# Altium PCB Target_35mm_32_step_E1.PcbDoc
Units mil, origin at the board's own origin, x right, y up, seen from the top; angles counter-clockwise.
Board outline 1400 x 1400 mil, 2 copper layers (Top Layer, Bottom Layer), stack 34.8 mil thick; 3 components, 0 nets, 2 pads, 0 vias.
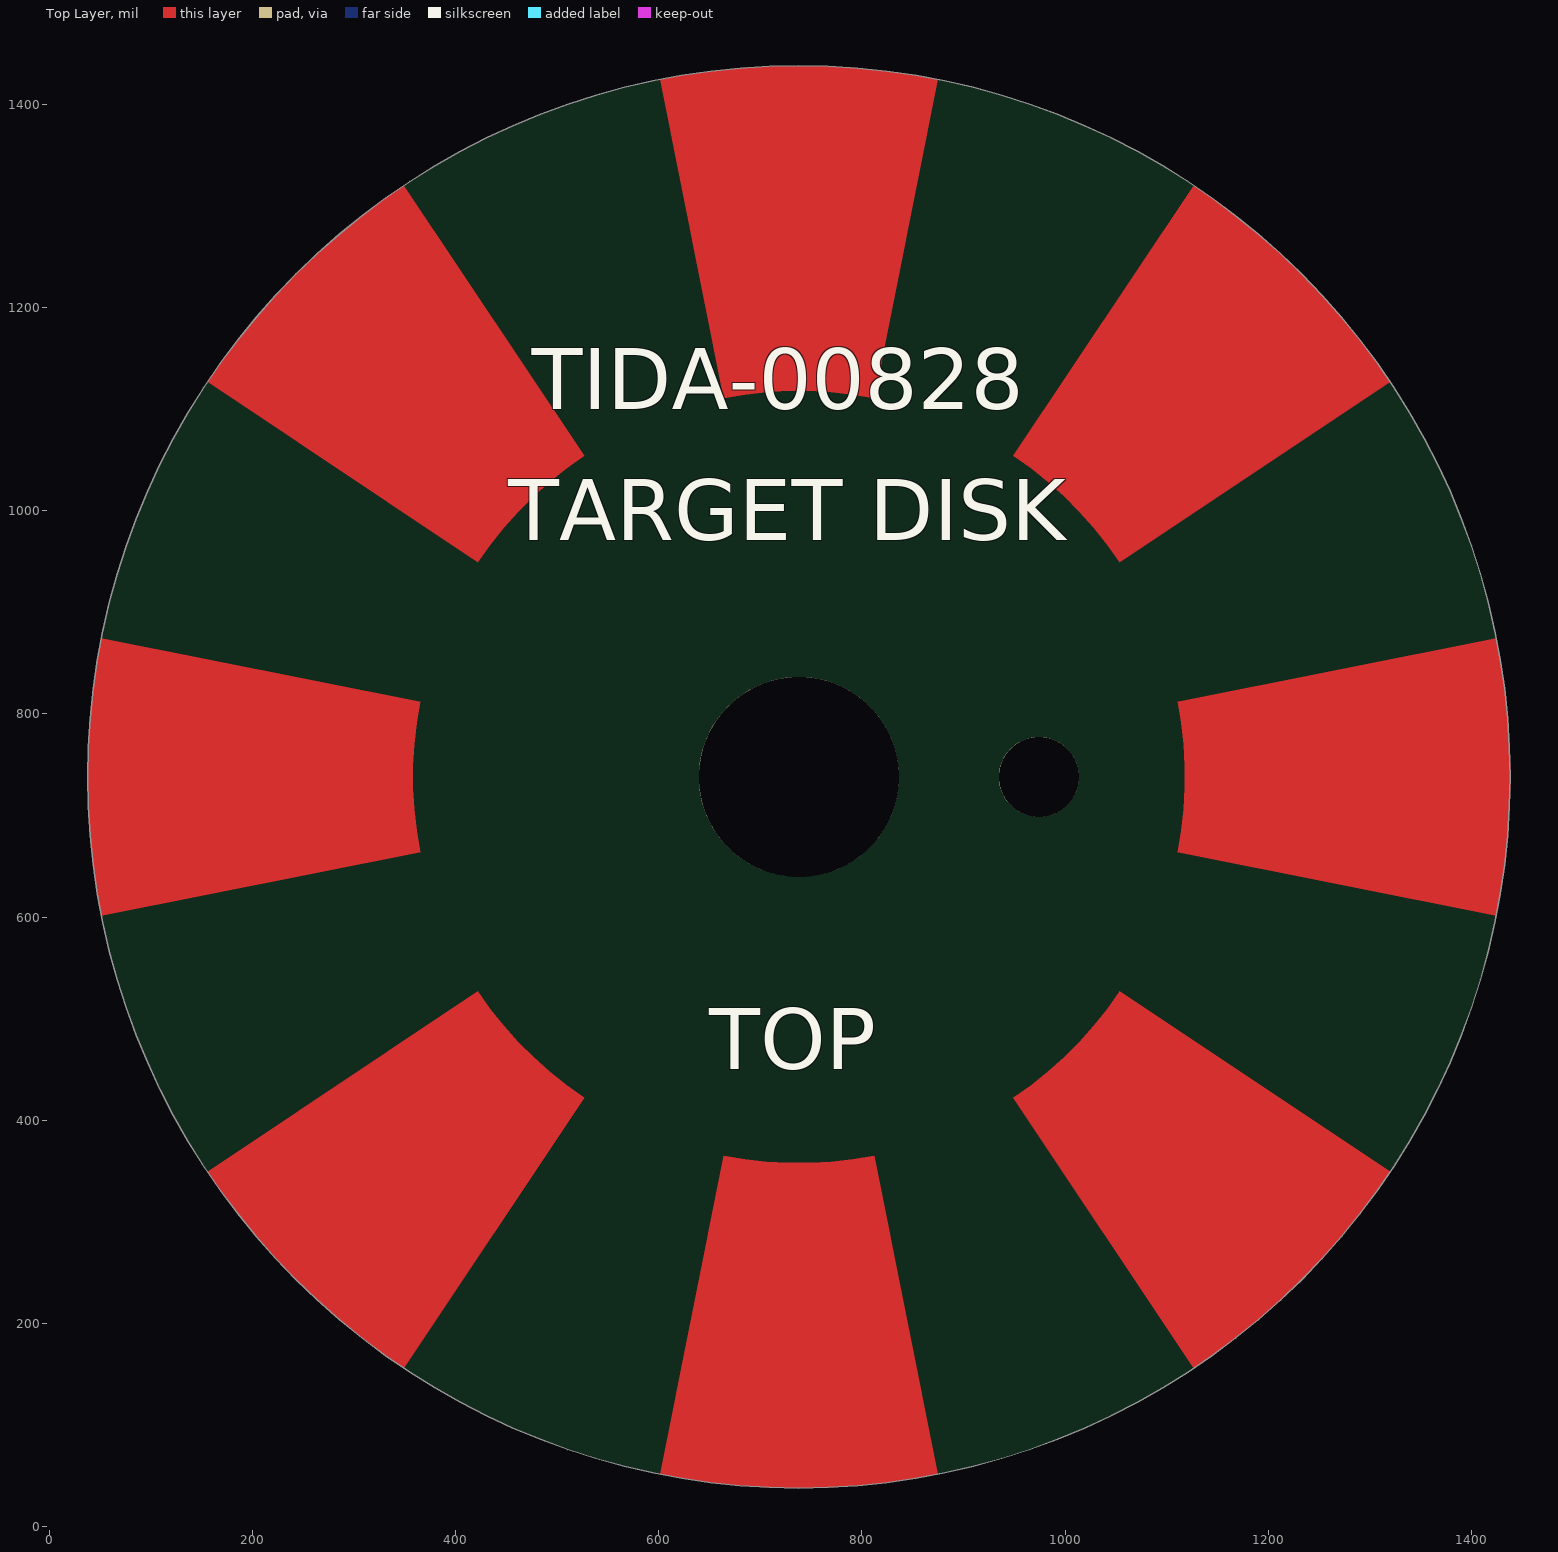
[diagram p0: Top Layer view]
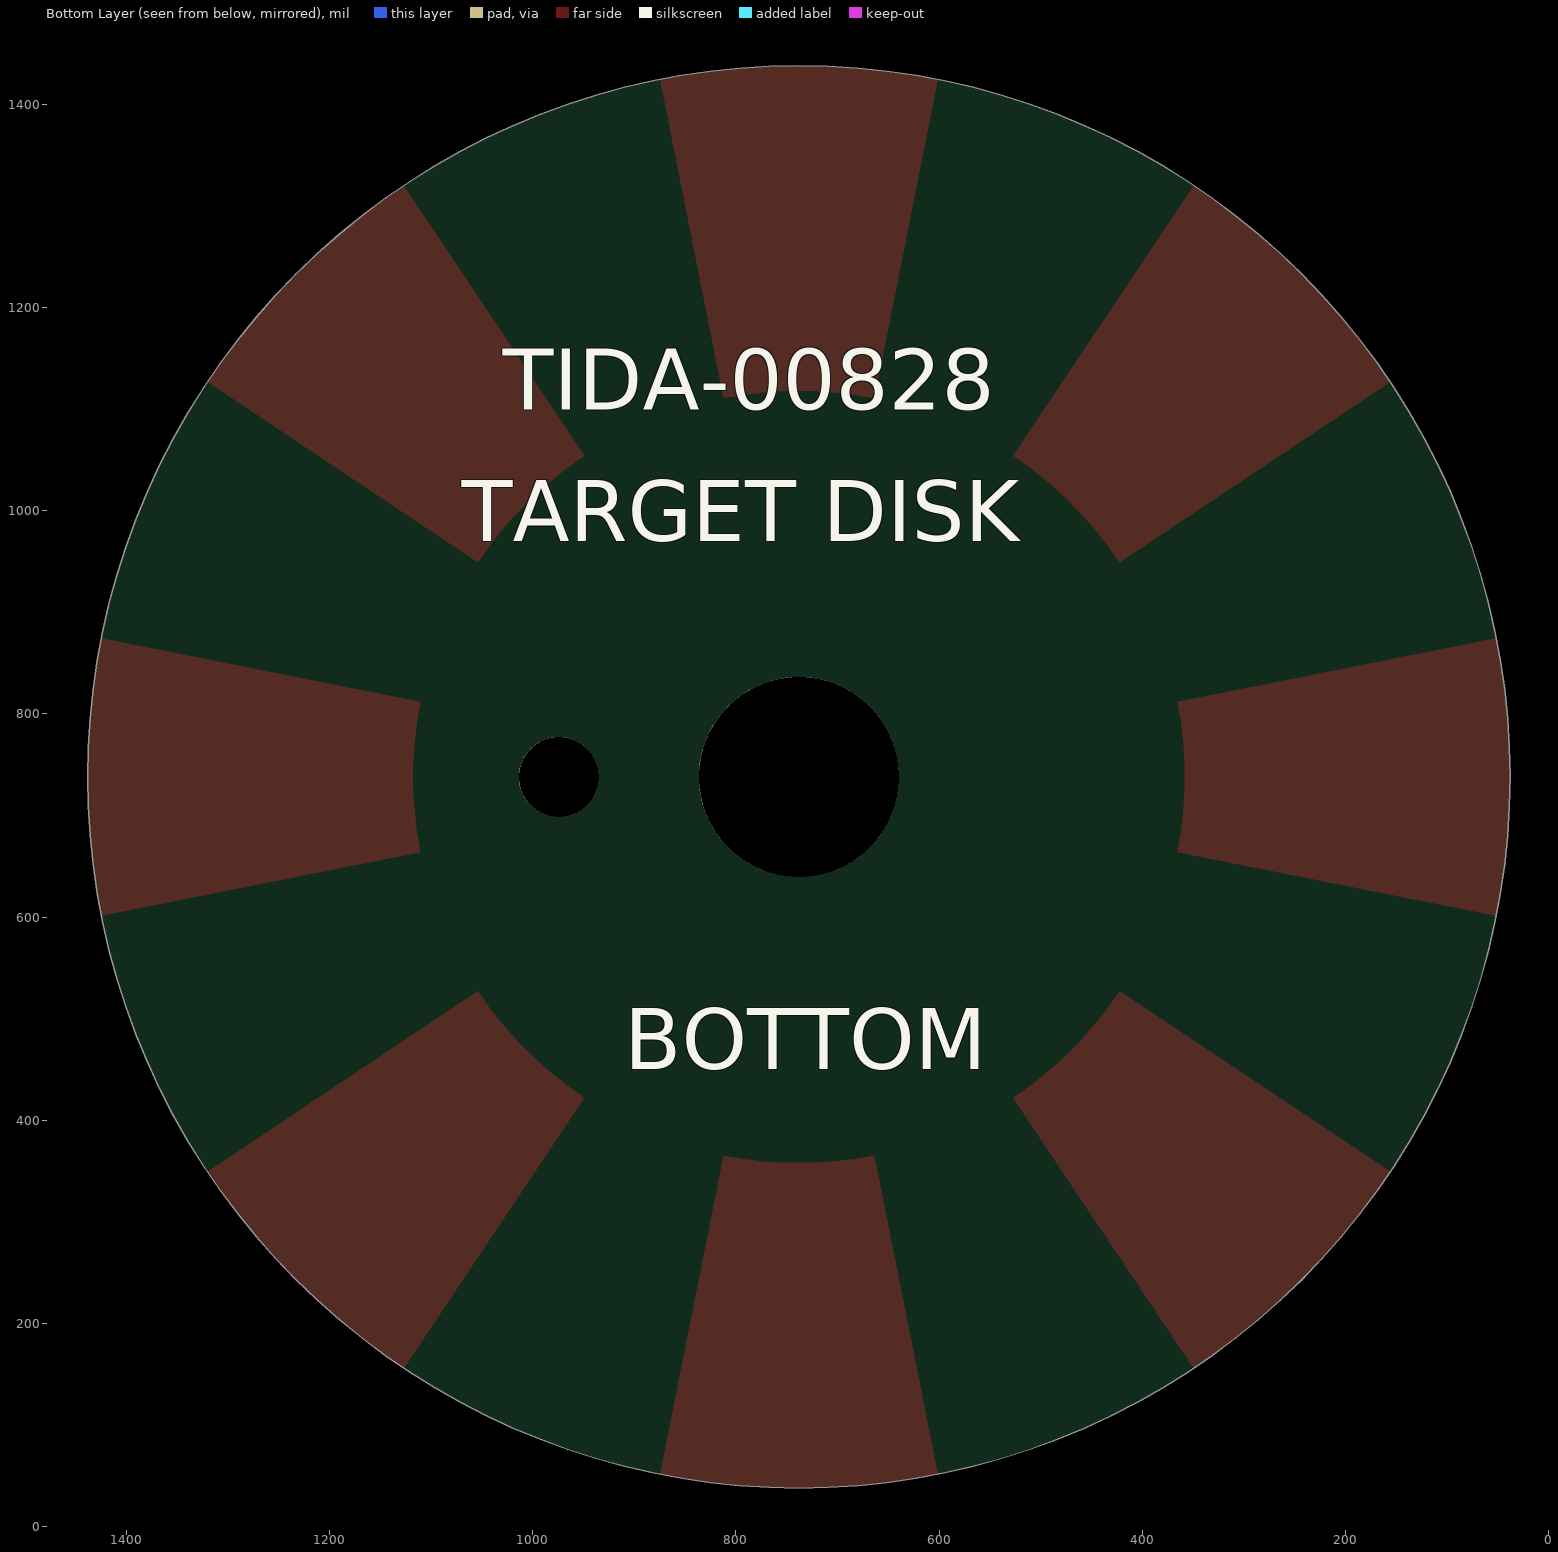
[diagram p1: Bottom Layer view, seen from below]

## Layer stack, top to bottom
Top Solder: solder mask 0.4, Solder Resist, Dk 3.5
Top Layer: signal copper 1.4
Dielectric1: core 32, FR-4, Dk 4.1
Bottom Layer: signal copper 1.4
Bottom Solder: solder mask 0.4, Solder Resist, Dk 3.5

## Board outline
738,38 cw(c738,738) 38,738 cw(c738,738) 738,1438 cw(c738,738) 1438,738 cw(c738,738)

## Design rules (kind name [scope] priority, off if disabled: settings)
AcuteAngle [All] p1: minimum=4.50000000000000E+0001 checktracksonly=FALSE
AssemblyTestPointUsage [All] p1: valid=2
Clearance Clearance_Keepouts [((IsTrack Or IsArc) And Not InPoly) And IsFree and IsKeepOut vs ((IsTrack Or IsArc) And Not InPoly) And IsFree and IsKeepOut] p1: gap=0
Clearance Clearance_BoardEdge_MountingHoles [OnCopper and InComponentClass('Mounting Holes') vs IsKeepOut] p2: gap=40
Clearance Clearance_BoardEdge_Poly [OnCopper and InPoly vs IsKeepOut] p3: gap=25
Clearance Clearance_BoardEdge [OnCopper and Not InComponentClass('Logo') and not InComponentClass('FiducialMark') and not InRegion(1000,500,4000,800) and Not IsKeepout vs IsKeepOut] p4: gap=75
Clearance Clearance_Poly [InPolygon] p5: gap=25
Clearance [All] p6: gap=7.87
ComponentClearance ComponentClearance_MountingHoles_FiducialMarks [InComponentClass('Mounting Holes') vs InComponentClass('FiducialMark')] p1: gap=50 collisioncheckmode=3 verticalgap=10 showdistances=FALSE
ComponentClearance ComponentClearance_Shunt [InComponentClass('Header') vs InComponentClass('Shunt')] p2: gap=0 collisioncheckmode=3 verticalgap=0 showdistances=FALSE
ComponentClearance ComponentClearance_Logo [InComponentClass('Logo')] p3: gap=50 collisioncheckmode=3 verticalgap=10 showdistances=FALSE
ComponentClearance ComponentClearance_ScrewToNut [(HasFootprint('NY PMS 440 0025 PH')) vs (HasFootprint('Keystone_1902C'))] p4: gap=5 collisioncheckmode=3 verticalgap=10 showdistances=FALSE
ComponentClearance ComponentClearance_MountingHoles [InComponentClass('Mounting Holes')] p5: gap=250 collisioncheckmode=3 verticalgap=100000 showdistances=FALSE
ComponentClearance ComponentClearance_SmallPassives [HasFootprint('0201*') or HasFootprint('0402*') or HasFootprint('0508') or HasFootprint('0603*') or HasFootprint('0612') or HasFootprint('0805*') or HasFootprint('0815*') or HasFootprint('0830*') or HasFootprint('1206*') or HasFootprint('1210*') or HasFootprint('1808*') or HasFootprint('1812*') or HasFootprint('1825*') or HasFootprint('2010*') or HasFootprint('2220*') or HasFootprint('2225*') or HasFootprint('2512*') or HasFootprint('2728*') or HasFootprint('3518*') vs HasFootprint('0201*') or HasFootprint('0402*') or HasFootprint('0508') or HasFootprint('0603*') or HasFootprint('0612') or HasFootprint('0805*') or HasFootprint('0815*') or HasFootprint('0830*') or HasFootprint('1206*') or HasFootprint('1210*') or HasFootprint('1808*') or HasFootprint('1812*') or HasFootprint('1825*') or HasFootprint('2010*') or HasFootprint('2220*') or HasFootprint('2225*') or HasFootprint('2512*') or HasFootprint('2728*') or HasFootprint('3518*')] p6: gap=20 collisioncheckmode=3 verticalgap=10 showdistances=FALSE
ComponentClearance ComponentClearance_THtoSMT [IsThruComponent vs IsSMTComponent] p7: gap=100 collisioncheckmode=3 verticalgap=30 showdistances=FALSE
ComponentClearance ComponentClearance_THtoTH [IsThruComponent vs IsThruComponent] p8: gap=118.11 collisioncheckmode=3 verticalgap=30 showdistances=FALSE
ComponentClearance [All] p9: gap=40 collisioncheckmode=3 verticalgap=10 showdistances=FALSE
DiffPairsRouting [All] p1: maxlimit=100 minlimit=10 mostfreqgap=10 toplayer_minwidth=15 toplayer_maxwidth=15 toplayer_prefwidth=15 bottomlayer_minwidth=15 bottomlayer_maxwidth=15 bottomlayer_prefwidth=15 maxuncoupledlength=1000
FabricationTestPointUsage TestPointUsage [All] p1: valid=2 allowmultiple=FALSE
FabricationTestpoint Testpoint [All] p1: side=3 testpointundercomponent=TRUE minsize=40 maxsize=100 preferedsize=60 minholesize=0 maxholesize=40 preferedholesize=32 testpointgrid=1 allowsidetop=TRUE allowsidebottom=TRUE usegrid=TRUE gridtolerance=0.01
FanoutControl Fanout_LCC [IsLCC] p1: bgadir=Out bgaviamode=Centered fanoutstyle=Auto fanoutdirection=Alternating viagrid=1 // Fanout_LCC (Default Rule)
FanoutControl Fanout_BGA [IsBGA] p2: bgadir=Out bgaviamode=Centered fanoutstyle=Auto fanoutdirection=Alternating viagrid=1 // Fanout_BGA (Default Rule)
FanoutControl Fanout_Default [All] p4: bgadir=Out bgaviamode=Centered fanoutstyle=Auto fanoutdirection=Alternating viagrid=1 // Fanout_Default (Default Rule)
FanoutControl Fanout_Small [(CompPinCount < 5)] p5: bgadir=Out bgaviamode=Centered fanoutstyle=Auto fanoutdirection=OutThenIn viagrid=1 // Fanout_Small (Default Rule)
HoleSize [All] p1: absolutevalues=TRUE maxlimit=251 minlimit=8 maxpercent=80.000 minpercent=20.000
MinimumAnnularRing MinimumAnnularRing_ThermalPadVias [IsVia and InAnyComponent] p1: minimumring=5.91
MinimumAnnularRing [All] p2: minimumring=9
MinimumSolderMaskSliver MinimumSolderMaskSliver_Logo [InComponentClass('Logo') vs InComponentClass('Logo')] p1: minsoldermaskwidth=0.7
MinimumSolderMaskSliver [All] p2: minsoldermaskwidth=3.94
PlaneConnect [All] p1: planeconnectstyle=Relief reliefexpansion=10 reliefentries=4 reliefconductorwidth=10 reliefairgap=10
PolygonConnect [All] p1: connectstyle=Relief reliefconductorwidth=10 reliefentries=4 polygonreliefangle="90 Angle" airgapwidth=10
RoutingVias ThermalPadVias [IsVia and InAnyComponent] p1: holewidth=7.87 width=19.68 viastyle="Through Hole" minholewidth=7.87 minwidth=19.68 maxholewidth=12.99 maxwidth=23.62
RoutingVias [All] p2: holewidth=16 width=34 viastyle="Through Hole" minholewidth=7.87 minwidth=26 maxholewidth=40 maxwidth=65
SilkToBoardRegionClearance [Not ((IsComment or IsDesignator) And (Hide <> 'False')) and not InRegion(1000,500,4000,800)] p1:
SilkToSilkClearance SilkToSilkClearance_Pb-FreeLogo [(HasFootprint('Pb-Free_Overlay_Medium') OR HasFootprint('Pb-Free_Overlay_Small')) vs (HasFootprint('Pb-Free_Overlay_Medium') OR HasFootprint('Pb-Free_Overlay_Small'))] p1: silktosilkclearance=0
SilkToSilkClearance [All] p2: silktosilkclearance=4
SilkToSolderMaskClearance SilkToComonentPadClearance [IsPad and InAnycomponent] p1: minsilkscreentomaskgap=5 clearancetoexposedcopper=TRUE
SilkToSolderMaskClearance "Silk to Solder Mask Opening" [All] p2: minsilkscreentomaskgap=4 clearancetoexposedcopper=FALSE
SolderMaskExpansion [All] p1: expansion=1.97
UnpouredPolygon [All] p1: allowunpoured=FALSE
Width [All] p1: maxlimit=100 minlimit=6 preferedwidth=10 checkconnectedcopper=TRUE
14 further rules are at their usual default settings.

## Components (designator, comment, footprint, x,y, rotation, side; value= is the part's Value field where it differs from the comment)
ZZ1 "This Assembly Note is for PCB labels only" AssemblyNoteLabel 185,3938 r0 top
ZZ2 "These assemblies are ESD sensitive, ESD precautions shall be observed." AssemblyNote 185,3829.11 r0 top
ZZ3 "These assemblies must be clean and free from flux and all contaminants. Use of no clean flux is not acceptable." AssemblyNote 185,3740.56 r0 top

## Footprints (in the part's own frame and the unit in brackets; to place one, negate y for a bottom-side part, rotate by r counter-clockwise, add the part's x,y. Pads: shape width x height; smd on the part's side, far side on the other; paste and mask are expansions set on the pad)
AssemblyNote [mil] "Assembly Note"
AssemblyNoteLabel [mil] "Assembly Note for PCB Labels"

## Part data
ZZ1: library part AssemblyNoteLabel
ZZ2 ZZ3: library part AssemblyNote

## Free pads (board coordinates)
  round 197 hole 197 unplated: 0(738,738)
  round 78.74 hole 78.74 unplated: 0(974.22,738)

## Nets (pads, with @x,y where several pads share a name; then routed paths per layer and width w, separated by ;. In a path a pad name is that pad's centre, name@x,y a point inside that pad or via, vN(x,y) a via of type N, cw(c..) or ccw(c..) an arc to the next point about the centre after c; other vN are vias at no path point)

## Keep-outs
Keep-Out Layer:
  text ".Layer_Name" at 577,-858.49 h60

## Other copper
Top Layer:
  region: 1126.9,1320.03 949.12,1053.96 cw(c738,738) 1053.96,949.12 1320.03,1126.9 ccw(c738,738)
  region: 601.44,1424.55 663.87,1110.7 cw(c738,738) 812.13,1110.7 874.56,1424.55 ccw(c738,738)
  region: 51.45,601.44 365.3,663.87 cw(c738,738) 365.3,812.13 51.45,874.56 ccw(c738,738)
  region: 874.56,51.45 812.13,365.3 cw(c738,738) 663.87,365.3 601.44,51.45 ccw(c738,738)
  region: 1424.55,874.56 1110.7,812.13 cw(c738,738) 1110.7,663.87 1424.55,601.44 ccw(c738,738)
  region: 155.97,1126.9 422.04,949.12 cw(c738,738) 526.88,1053.96 349.1,1320.03 ccw(c738,738)
  region: 349.1,155.97 526.88,422.04 cw(c738,738) 422.04,526.88 155.97,349.1 ccw(c738,738)
  region: 1320.03,349.1 1053.96,526.88 cw(c738,738) 949.12,422.04 1126.9,155.97 ccw(c738,738)
  text ".Layer_Name" at 577,-858.49 h60
Bottom Layer:
  text ".Layer_Name" at 577,-858.49 h60

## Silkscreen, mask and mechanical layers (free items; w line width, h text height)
Top Overlay:
  text "TIDA-00828" at 475,1100 h60
  text "TARGET DISK" at 451.86,970.64 h60
  text "TOP" at 650,450 h60
  text ".Layer_Name" at 577,-858.49 h60
Bottom Overlay:
  text "TIDA-00828" at 1029.68,1099.09 h60
  text "TARGET DISK" at 1070,970 h60
  text "BOTTOM" at 910,450 h60
  text ".Layer_Name" at 577,-858.49 h60
Top Paste:
  text ".Layer_Name" at 577,-858.49 h60
Bottom Paste:
  text ".Layer_Name" at 577,-858.49 h60
Top Solder:
  text ".Layer_Name" at 577,-858.49 h60
  text ".Layer_Name" at 577,-858.49 h60
Bottom Solder:
  text ".Layer_Name" at 577,-858.49 h60
Drill Guide:
  text ".Layer_Name" at 577,-858.49 h60
M1 Board Outline:
  circle w4: c738,738 r700
  text ".Layer_Name" at 577,-858.49 h60
M2 Board Dimensions:
  rectangle: 125,-400 500,-275
  rectangle: 0,-275 125,-150
  lines w7: 0,-275 1000,-275 ; 125,-400 125,-150 ; 250,-400 250,-150 ; 500,-400 500,-150 ; 750,-400 750,-150 ; 0,-400 0,-150 1000,-150 1000,-400 0,-400
  text ".Layer_Name" at 577,-858.49 h60
M3 3D STEP Top:
  text ".Layer_Name" at 577,-858.49 h60
M4 3D STEP Bottom:
  text ".Layer_Name" at 577,-858.49 h60
M5 Assembly Top:
  lines w10: -292,-930.17 6308,-930.17 ; -292,-726.83 6310,-726.83 ; -292,-523.5 -292,-1133.5 3713,-1133.5 6310,-1133.5 6310,-523.5 -291.5,-523.5 -291.5,-1133.5 1284,-1133.5 ; 2173,-1133.5 2173,-523.5 ; 3440,-726.83 3440,-523.5 ; 4280,-726.83 4280,-523.5 ; 4902,-1140 4902,-937.17
  text "COMPONENTS MARKED 'DNP' SHOULD NOT BE POPULATED." at 1153.5,-318.5 h60
  text "ASSEMBLY VARIANT:" at 1153,-434 h60
  text ".VariantName" at 2189,-434 h60
  text "PCB VIEWED FROM TOP SIDE" at -228.5,-655.67 h60
  text "BOARD #:" at 2248,-655.67 h60
  text ".PRJ_Number" at 2793.5,-655.67 h60
  text "REV:" at 3638,-655.67 h60
  text ".PCB_Rev" at 3929.5,-655.67 h60
  text "SVN REV:" at 4476,-655.67 h60
  text ".VersionControl_RevNumber" at 4982,-655.67 h60
  text "TID #:" at 2248,-859 h60
  text ".TID" at 2793.5,-859 h60
  text "PLOT NAME =" at -228.5,-1064.34 h60
  text ".plot_File_Name" at 577,-1064.34 h60
  text "GENERATED    :" at 2250,-1064.34 h60
  text ".Print_Date" at 3119.5,-1064.34 h60
  text ".Print_Time" at 3848.5,-1064.34 h60
  text "TEXAS INSTRUMENTS" at 5113,-1064.34 h60
M6 Assembly Bottom:
  lines w10: -292.5,-727.33 6309.5,-727.33 ; -290.5,-930.67 6309.5,-930.67 ; 1115.5,-1140.5 1115.5,-937.67 ; 1737.5,-727.33 1737.5,-524 ; 2577.5,-727.33 2577.5,-524 ; 3844.5,-1134 3844.5,-524 ; 4733.5,-1134 6309,-1134 6309,-524 -292.5,-524 -292.5,-1134 2304.5,-1134 6309.5,-1134 6309.5,-524
  text "COMPONENTS MARKED 'DNP' SHOULD NOT BE POPULATED." at 6102,-318 h60
  text ".VariantName" at 5058,-434 h60
  text "ASSEMBLY VARIANT:" at 6097,-434 h60
  text ".VersionControl_RevNumber" at 1035.5,-656.17 h60
  text "SVN REV:" at 1541.5,-656.17 h60
  text ".PCB_Rev" at 2088,-656.17 h60
  text "REV:" at 2379.5,-656.17 h60
  text ".PRJ_Number" at 3224,-656.17 h60
  text "BOARD #:" at 3769.5,-656.17 h60
  text "PCB VIEWED FROM BOTTOM SIDE" at 6246,-656.17 h60
  text ".TID" at 3224,-859.5 h60
  text "TID #:" at 3769.5,-859.5 h60
  text "TEXAS INSTRUMENTS" at 904.5,-1064.84 h60
  text ".Print_Time" at 2169,-1064.84 h60
  text ".Print_Date" at 2898,-1064.84 h60
  text "GENERATED    :" at 3767.5,-1064.84 h60
  text ".plot_File_Name" at 5440.5,-1064.84 h60
  text "PLOT NAME =" at 6246,-1064.84 h60
M9 Title Sheet:
  drawing of 57 lines, arcs and shapes, not listed
  text "1" at 739.84,8036.5 h70
  text "2" at 3235.5,8036.5 h70
  text "3" at 5724.84,8036.5 h70
  text "4" at 8231.51,8036.5 h70
  text "5" at 10730.5,8036.5 h70
  text "6" at 13235.5,8036.5 h70
  text "A" at -416.5,6893.5 h70
  text "A" at 14383.5,6893.5 h70
  text "B" at -416.5,4513.5 h70
  text "B" at 14383.5,4513.5 h70
  text "C" at -416.5,2138.5 h70
  text "C" at 14383.5,2138.5 h70
  text "PROJECT TITLE:" at 11343.5,277.5 h45
  text ".PRJ_Title" at 11393.5,144.17 h70
  text "DESIGNED FOR:" at 11343.5,-23.5 h45
  text ".PRJ_Customer" at 11393.5,-163.5 h70
  text "D" at -416.5,-231.5 h70
  text "D" at 14383.5,-231.5 h70
  text "FILE NAME:" at 11343.5,-323.5 h45
  text ".PCB_File_Name_No_Path" at 11393.5,-443.5 h70
  text "Texas Instruments (TI) and/or its licensors do not warrant the accuracy or completeness of this specification" at 6374,-605.34 h45
  text "ENGINEER:" at 11343.5,-613.5 h45
  text "LAYOUT BY:" at 12848.5,-613.5 h45
  text "or any information contained therein. TI and/or its licensors do not warrant that this design will meet" at 6329.01,-718 h45
  text ".PRJ_Engineer" at 11393.5,-768.49 h70
  text ".PCB_Layout" at 12899,-768.49 h70
  text "the specifications, will be suitable for your application or fit for any particular purpose, or will operate in" at 6329.01,-830.67 h45
  text ".Layer_Name" at 577,-858.49 h60
  text "ALTIUM DESIGNER VERSION:" at 12848.5,-923.5 h45
  text "an implementation. TI and/or its licensors do not warrant that the design is production worthy. You should" at 6329.01,-943.33 h45
  text "completely validate and test your design implementation to confirm the system functionality for your application." at 6374,-1056 h45
  text ".print_Scale" at 11393.5,-1056.83 h70
  text ".Application_BuildNumber" at 12899,-1056.83 h70
  text "1" at 739.84,-1263.5 h70
  text "2" at 3235.5,-1263.5 h70
  text "3" at 5724.84,-1263.5 h70
  text "4" at 8231.51,-1263.5 h70
  text "5" at 10730.5,-1263.5 h70
  text "6" at 13235.5,-1263.5 h70
M10 Fab Notes:
  drawing of 189 lines, arcs and shapes, not listed
  text "BOARD THICKNESS MINIMUM 0.77mm!" at 9890,6870 h60
  text "DESIGN INFORMATION" at 12381.02,6028 h60
  text "N/A" at 12740,5860 h60
  text "MIN. TRACK WIDTH:" at 11736.46,5848 h60
  text "MIL" at 12987.46,5848 h60
  text "MIN. CLEARANCE:" at 11736.46,5716 h60
  text "10" at 12772.7,5716 h60
  text "MIL" at 12987.46,5716 h60
  text "N/A" at 12710,5590 h60
  text "MIN. VIA PAD SIZE:" at 11736.46,5584 h60
  text "MIL" at 12987.46,5584 h60
  text "0.05mm (2MIL)" at 12431.46,5442.29 h60
  text "MINIMUM ANNULAR RING" at 11407.23,5438 h60
  text "EXTERNAL" at 13139.46,5438 h60
  text "PER" at 11607.23,5320 h60
  text "IPC-D-275 CLASS 2 LEVEL C" at 11827.23,5320 h60
  text "MIL, HOLES" at 13315.46,5207.71 h60
  text "+/-" at 12923,5207 h60
  text "+/-" at 13777,5207 h60
  text "REGISTRATION TOLERANCES:" at 11407.23,5202 h60
  text "METAL" at 12607,5202 h60
  text "5" at 13183.2,5202 h60
  text "3" at 14016.2,5202 h60
  text "MIL" at 14132.46,5202 h60
  text "+/-" at 13777,5089 h60
  text "HOLE SIZE TOLERANCE (UNLESS OTHERWISE SPECIFIED):" at 11407.23,5084 h60
  text "3" at 14016.2,5084 h60
  text "MIL" at 14132.46,5084 h60
  text "MATERIAL:" at 11332.46,4874.54 h60
  text "FR-4 High Tg" at 12318.9,4734.21 h60
  text "FR-408" at 11753.46,4725.64 h60
  text "OTHER" at 13241.46,4725.64 h60
  text "X" at 12164,4722 h60
  text "62 MIL (1.6mm) +/-10%" at 12073.56,4562.92 h60
  text "X" at 13180,4560 h60
  text "OTHER" at 13300,4560 h60
  text "0.87mm+/-10%" at 13580,4560 h60
  text "THICKNESS:" at 11407.23,4558.64 h60
  text "TOLERANCE:" at 11407.23,4400.64 h60
  text "X" at 12246.53,4400.64 h60
  text "ANSI IPC-6012 TYPE 3 CLASS 2" at 12433.48,4400.64 h60
  text "OTHER +/-" at 12433.46,4244.64 h60
  text "BOW & TWIST:" at 11407.23,4087.64 h60
  text "X" at 12246.53,4087.64 h60
  text "ANSI IPC-6012 TYPE 3 CLASS 2" at 12433.48,4087.64 h60
  text "OTHER +/-" at 12433.46,3929.13 h60
  text "DRILLING:" at 11332.46,3790.64 h60
  text "REFERENCE:" at 11407.23,3673.64 h60
  text "X" at 12055.46,3673.64 h60
  text "AS SHOWN" at 12242.46,3673.64 h60
  text "X" at 12956.46,3673.64 h60
  text "NC_DRILL FILES" at 13093.46,3673.64 h60
  text "PTH MIN COPPER THICKNESS:" at 11407.23,3515.64 h60
  text "X" at 12757.46,3515.64 h60
  text "1MIL" at 12894.46,3515.64 h60
  text "OTHER" at 13391.46,3515.64 h60
  text "BOARD FINISH:" at 11332.46,3356.64 h60
  text "SILKSCREEN:" at 11487.68,3238.64 h60
  text "X" at 12436.46,3238.64 h60
  text "TOP" at 12562.46,3238.64 h60
  text "X" at 12946.46,3238.64 h60
  text "BOTTOM" at 13073.46,3238.64 h60
  text "SILKSCREEN COLOR:" at 11487.68,3071.64 h60
  text "X" at 12435.42,3071.64 h60
  text "WHITE" at 12562.46,3071.64 h60
  text "OTHER" at 13073.46,3071.64 h60
  text "BLACK" at 13670,2940 h60
  text "X" at 13150,2920 h60
  text "GREEN" at 12693.46,2912.44 h60
  text "OTHER" at 13311.46,2912.44 h60
  text "SOLDER RESIST COLOR:" at 11487.68,2901.64 h60
  text "X" at 12566.42,2742.44 h60
  text "MATTE" at 12693.46,2742.44 h60
  text "SEMI-GLOSS" at 13311,2741.8 h60
  text "NO THIEVING ALLOWED ON ANY LAYERS" at 25,2675 h60
  text "IMMERSION GOLD (ENIG)" at 12393.46,2553.92 h60
  text "ENEPIG" at 13731,2550.64 h60
  text "SURFACE FINISH:" at 11332.46,2549.64 h60
  text "X" at 12206.51,2549.64 h60
  text "NO FEATURE IS ALLOWED ON THE PCB." at 25,2525 h60
  text "IMM. TIN/SILVER OR EQUIV" at 11662,2392.64 h60
  text "OTHER" at 13093.46,2392.64 h60
  text "ALL MARKING AND FAB LOGO SILKSCREENS MUST BE WITHIN THE RAILS ON THE PANEL." at 25,2350 h60
  text "ARRAY/PANEL:" at 11332.46,2213.64 h60
  text "CUT AND TRIM PER M1 BOARD OUTLINE" at 12393.46,2209.35 h60
  text "NO IPC356 NETLIST IS PROVIDED BY DESIGN." at 25,2150 h60
  text "X" at 12210,2070 h60
  text "N.C. ROUTE" at 12393.46,2057.64 h60
  text "V. SCORE" at 13259.46,2057.64 h60
  text "IT IS ACCEPTABLE TO PULL COPPER BACK 8-15 MILS FROM THE EDGE." at 25,1950 h60
  text "CERTIFICATION:" at 11332.46,1920.64 h60
  text "MATERIALS AND WORKMANSHIP FOR ALL PCBS" at 12057.46,1920.64 h60
  text "TO MEET OR EXCEED THE REQUIREMENTS OF:" at 12057.46,1822.64 h60
  text "X" at 11683.96,1686.13 h60
  text "ANSI IPC-A-600F CLASS ->" at 11822.96,1686.13 h60
  text "X" at 13462.02,1686.13 h60
  text "2" at 13580.96,1686.14 h60
  text "1" at 13265.96,1684.64 h60
  text "3" at 13934.96,1684.64 h60
  text "X" at 11686.02,1526.64 h60
  text "UL 94V-0" at 11822.96,1526.64 h60
  text "X" at 12498.02,1526.64 h60
  text "RoHS" at 12634.96,1526.64 h60
  text "OTHER" at 13279.36,1526.64 h60
  text "PER ORDER" at 13676.42,1526.64 h60
  text "ADDITIONAL REQUIREMENTS:" at 11332.46,1385.64 h60
  text "MICROSECTION:" at 11407.23,1270.64 h60
  text "YES" at 12312.96,1270.64 h60
  text "REQUIRED" at 13174.46,1114.49 h60
  text "BARE BOARD ELEC. TEST:" at 11407.23,1111.64 h60
  text "NONE" at 12712.96,1111.64 h60
  text "X" at 13047.46,1111.64 h60
  text "PER ORDER" at 13766.46,1111.64 h60
  text "MANUFACTURER'S UL:" at 11407.23,954.64 h60
  text "RAIL" at 12572.96,950.35 h60
  text "METAL" at 13064.77,950.35 h60
  text "X" at 13440,950 h60
  text "SILK" at 13576.46,950.35 h60
  text ".Layer_Name" at 577,-858.49 h60
M11 Gerber Information:
  lines w10: -292,-930.17 6308,-930.17 ; -292,-726.83 6310,-726.83 ; -292,-523.5 -292,-1133.5 3713,-1133.5 6310,-1133.5 6310,-523.5 -291.5,-523.5 -291.5,-1133.5 1284,-1133.5 ; 2173,-1133.5 2173,-523.5 ; 3440,-726.83 3440,-523.5 ; 4280,-726.83 4280,-523.5 ; 4902,-1140 4902,-937.17
  text "ALL ARTWORK VIEWED FROM TOP SIDE" at -228.5,-655.67 h60
  text "BOARD #:" at 2248,-655.67 h60
  text ".PRJ_Number" at 2793.5,-655.67 h60
  text "REV:" at 3638,-655.67 h60
  text ".PCB_Rev" at 3929.5,-655.67 h60
  text "SVN REV:" at 4476,-655.67 h60
  text ".VersionControl_RevNumber" at 4982,-655.67 h60
  text "LAYER NAME =" at -228.5,-858.49 h60
  text "TID #:" at 2248,-859 h60
  text ".TID" at 2793.5,-859 h60
  text "PLOT NAME =" at -228.5,-1064.34 h60
  text ".plot_File_Name" at 577,-1064.34 h60
  text "GENERATED    :" at 2250,-1064.34 h60
  text ".Print_Date" at 3119.5,-1064.34 h60
  text ".Print_Time" at 3848.5,-1064.34 h60
  text "TEXAS INSTRUMENTS" at 5113,-1064.34 h60
M12 Stackup:
  drawing of 191 lines, arcs and shapes, not listed
  text "Layer" at 9800.58,7850 h60
  text "Name" at 10210.49,7850 h60
  text "Material" at 11140.23,7850 h60
  text "Thickness" at 12000,7850 h60
  text "Constant" at 12649.84,7850 h60
  text "Board Layer Stack" at 13219.7,7850 h60
  text "1" at 9800.58,7730 h60
  text "Top Overlay" at 10210.49,7730 h60
  text "2" at 9800.58,7610 h60
  text "Top Solder" at 10210.49,7610 h60
  text "Solder Resist" at 11140.23,7610 h60
  text "0.40mil" at 12000,7610 h60
  text "3.5" at 12649.84,7610 h60
  text "3" at 9800.58,7490 h60
  text "Top Layer" at 10210.49,7490 h60
  text "Copper" at 11140.23,7490 h60
  text "1.40mil" at 12000,7490 h60
  text "4" at 9800.58,7370 h60
  text "Dielectric1" at 10210.49,7370 h60
  text "FR-4" at 11140.23,7370 h60
  text "32.00mil" at 12000,7370 h60
  text "4.1" at 12649.84,7370 h60
  text "5" at 9800.58,7250 h60
  text "Bottom Layer" at 10210.49,7250 h60
  text "Copper" at 11140.23,7250 h60
  text "1.40mil" at 12000,7250 h60
  text "6" at 9800.58,7130 h60
  text "Bottom Solder" at 10210.49,7130 h60
  text "Solder Resist" at 11140.23,7130 h60
  text "0.40mil" at 12000,7130 h60
  text "3.5" at 12649.84,7130 h60
  text "7" at 9800.58,7010 h60
  text "Bottom Overlay" at 10210.49,7010 h60
  text ".Layer_Name" at 577,-858.49 h60
M13 Component Bodies Top:
  text ".Layer_Name" at 577,-858.49 h60
M14 Component Bodies Bottom:
  text ".Layer_Name" at 577,-858.49 h60
M15 Courtyards Top:
  text ".Layer_Name" at 577,-858.49 h60
M16 Courtyards Bottom:
  text ".Layer_Name" at 577,-858.49 h60
Drill Drawing:
  lines w1: 5667.83,3046.84 5717.6,3046.84 5717.6,3096.61 5667.83,3096.61 5667.83,3046.84 ; 5667.83,3221.04 5692.72,3196.16 5717.6,3221.04 5692.72,3245.93 5667.83,3221.04 ; 5677.78,3056.79 5707.65,3056.79 5707.65,3086.65 5677.78,3086.65 5677.78,3056.79
  lines w12: 5600,3002.04 7718.02,3002.04 ; 5600,3300.68 7718.02,3300.68 ; 5970.36,2852.72 5970.36,3450 ; 6327.36,2852.72 6327.36,3450 ; 6988.93,2852.72 6988.93,3450 ; 7273.07,2852.72 7273.07,3450 ; 5600,2852.72 7718.02,2852.72 7718.02,3450 5600,3450 5600,2852.72
  text "Symbol" at 5689.59,3345.48 h72
  text "Quantity" at 6015.16,3345.48 h72
  text "Finished Hole Size" at 6372.16,3345.48 h72
  text "Plated" at 7033.72,3345.48 h72
  text "Hole Type" at 7317.86,3345.48 h72
  text "1" at 6015.16,3196.16 h60
  text "78.74mil (2.000mm)" at 6372.16,3196.16 h60
  text "NPTH" at 7033.72,3196.16 h60
  text "Round" at 7317.86,3196.16 h60
  text "1" at 6015.16,3046.84 h60
  text "197.00mil (5.004mm)" at 6372.16,3046.84 h60
  text "NPTH" at 7033.72,3046.84 h60
  text "Round" at 7317.86,3046.84 h60
  text "2 Total" at 6015.16,2897.52 h60
  text ".Layer_Name" at 577,-858.49 h60

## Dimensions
0,-400 to 1000,-400 on M2 Board Dimensions
738,738 to 2820,750 on M2 Board Dimensions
